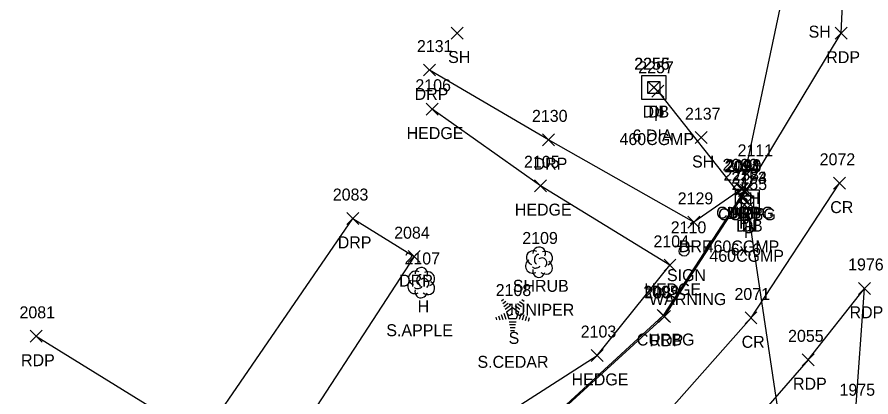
# Model space of a CAD drawing. Extents: x 462930 to 463548, y 29607 to 30453.
# Drawn here: x 463350.88 to 463394.45, y 30226.91 to 30246.27 of the extents above; entities that cross this region are included whole.
import ezdxf

# ---------------------------------------------------------------- set-up
doc = ezdxf.new("R2010")
doc.units = 0
for name, color, linetype in [('D_A', 7, 'Continuous'), ('D_C', 7, 'Continuous'), ('D_I', 7, 'Continuous'), ('D_TIC', 7, 'Continuous'), ('DCP', 7, 'Continuous'), ('DS', 7, 'Continuous'), ('L_A', 7, 'Continuous'), ('L_C', 7, 'Continuous'), ('L_I', 7, 'Continuous'), ('L_TIC', 7, 'Continuous'), ('LAHR', 7, 'Continuous'), ('LSH', 7, 'Continuous'), ('LTC', 7, 'Continuous'), ('LTD', 7, 'Continuous'), ('P_A', 7, 'Continuous'), ('P_I', 7, 'Continuous'), ('P_TIC', 7, 'Continuous'), ('PET', 7, 'Continuous'), ('PRC', 7, 'Continuous'), ('R_A', 7, 'Continuous'), ('R_I', 7, 'Continuous'), ('R_TIC', 7, 'Continuous'), ('RC', 7, 'Continuous'), ('RDP', 7, 'Continuous'), ('S_A', 7, 'Continuous'), ('S_C', 7, 'Continuous'), ('S_I', 7, 'Continuous'), ('SSGN', 7, 'Continuous')]:
    doc.layers.add(name, color=color, linetype=linetype)

msp = doc.modelspace()

# ---------------------------------------------------------------- linework, layer by layer
at = {"layer": 'D_TIC'}
for points in [[(463383.071, 30242.367), (463383.681, 30242.977)], [(463383.681, 30242.367), (463383.071, 30242.977)], [(463383.268, 30242.182), (463383.878, 30242.792)], [(463383.878, 30242.182), (463383.268, 30242.792)], [(463387.614, 30236.711), (463388.224, 30237.321)], [(463388.224, 30236.711), (463387.614, 30237.321)], [(463387.844, 30236.554), (463388.454, 30237.164)], [(463388.454, 30236.554), (463387.844, 30237.164)], [(463387.855, 30236.235), (463388.465, 30236.845)], [(463388.465, 30236.235), (463387.855, 30236.845)]]:
    msp.add_lwpolyline(points, dxfattribs=at)
at = {"layer": 'DCP'}
for points in [[(463383.573, 30242.487), (463387.919, 30237.016)], [(463388.16, 30236.54), (463390.706, 30219.484)]]:
    msp.add_lwpolyline(points, dxfattribs=at)
at = {"layer": 'DS'}
for p, q in [((463382.765, 30243.281), (463383.984, 30243.281)), ((463382.765, 30242.062), (463382.765, 30243.281)), ((463383.984, 30243.281), (463383.984, 30242.062)), ((463383.07, 30242.367), (463383.07, 30242.976)), ((463383.07, 30242.976), (463383.679, 30242.976)), ((463383.376, 30242.672), (463383.376, 30242.672)), ((463383.376, 30242.672), (463383.376, 30242.672)), ((463383.679, 30242.976), (463383.679, 30242.367)), ((463383.679, 30242.367), (463383.07, 30242.367)), ((463383.984, 30242.062), (463382.765, 30242.062)), ((463387.538, 30237.468), (463388.757, 30237.468)), ((463387.538, 30236.249), (463387.538, 30237.468)), ((463388.757, 30237.468), (463388.757, 30236.249)), ((463387.843, 30236.554), (463387.843, 30237.163)), ((463387.843, 30237.163), (463388.452, 30237.163)), ((463388.452, 30237.163), (463388.452, 30236.554)), ((463388.452, 30236.554), (463387.843, 30236.554)), ((463388.149, 30236.859), (463388.149, 30236.859)), ((463388.149, 30236.859), (463388.149, 30236.859)), ((463388.757, 30236.249), (463387.538, 30236.249))]:
    msp.add_line(p, q, dxfattribs=at)
at = {"layer": 'L_TIC'}
for points in [[(463373.034, 30245.145), (463373.644, 30245.755)], [(463373.644, 30245.145), (463373.034, 30245.755)], [(463371.764, 30241.269), (463372.374, 30241.879)], [(463372.374, 30241.269), (463371.764, 30241.879)], [(463385.48, 30239.82), (463386.09, 30240.43)], [(463386.09, 30239.82), (463385.48, 30240.43)], [(463387.819, 30237.952), (463388.429, 30238.562)], [(463388.429, 30237.952), (463387.819, 30238.562)], [(463377.287, 30237.369), (463377.897, 30237.979)], [(463377.897, 30237.369), (463377.287, 30237.979)], [(463383.894, 30233.312), (463384.504, 30233.922)], [(463384.504, 30233.312), (463383.894, 30233.922)], [(463380.183, 30228.717), (463380.793, 30229.327)], [(463380.793, 30228.717), (463380.183, 30229.327)]]:
    msp.add_lwpolyline(points, dxfattribs=at)
at = {"layer": 'LAHR'}
msp.add_lwpolyline([(463364.966, 30224.308), (463371.552, 30223.305), (463380.488, 30229.022), (463384.199, 30233.617), (463377.592, 30237.674), (463372.069, 30241.574)], dxfattribs=at)
at = {"layer": 'LSH'}
msp.add_line((463377.51, 30233.791), (463377.51, 30233.791), dxfattribs=at)
msp.add_line((463377.51, 30233.791), (463377.51, 30233.791), dxfattribs=at)
msp.add_arc((463377.524, 30234.228), 0.319, 335.5272, 180.9563, dxfattribs=at)
for centre, major_axis, ratio, start_param, end_param in [((463377.269, 30233.994), (0.369, -0.156), 0.895232, 1.570796, 4.712389), ((463377.827, 30233.969), (-0.348, -0.147), 0.949671, 1.570796, 4.712389), ((463377.18, 30233.575), (0.178, -0.317), 0.959034, 3.141593, 6.283185), ((463377.446, 30233.931), (-0.063, -0.241), 0.645439, 3.141593, 6.283185), ((463377.662, 30233.74), (-0.152, 0.203), 0.989748, 3.141593, 6.283185), ((463377.51, 30233.334), (0.081, 0.323), 0.942809, 1.570796, 4.712389), ((463377.37, 30233.562), (-0.19, -0.025), 0.423636, 0, 3.141593), ((463377.815, 30233.537), (-0.332, 0.241), 0.841452, 1.570796, 4.712389)]:
    msp.add_ellipse(centre, major_axis=major_axis, ratio=ratio, start_param=start_param, end_param=end_param, dxfattribs=at)
at = {"layer": 'LTC'}
for p, q in [((463375.6, 30231.809), (463375.708, 30231.888)), ((463375.664, 30231.667), (463375.825, 30231.784)), ((463375.728, 30231.525), (463375.942, 30231.681)), ((463376.41, 30231.67), (463376.617, 30231.519)), ((463376.523, 30231.776), (463376.69, 30231.654)), ((463376.636, 30231.882), (463376.763, 30231.789)), ((463375.792, 30231.383), (463376.059, 30231.578)), ((463375.86, 30231.245), (463376.168, 30231.468)), ((463375.86, 30231.245), (463375.978, 30230.881)), ((463376.168, 30231.468), (463376.472, 30231.247)), ((463376.296, 30231.564), (463376.543, 30231.384)), ((463376.472, 30231.247), (463376.353, 30230.881)), ((463375.305, 30230.98), (463375.351, 30230.837)), ((463375.444, 30231.046), (463375.508, 30230.847)), ((463375.583, 30231.112), (463375.665, 30230.857)), ((463375.721, 30231.178), (463375.822, 30230.867)), ((463376.353, 30230.881), (463375.978, 30230.881)), ((463376.606, 30231.165), (463376.503, 30230.848)), ((463376.741, 30231.089), (463376.653, 30230.819)), ((463376.877, 30231.012), (463376.804, 30230.79)), ((463377.012, 30230.936), (463376.955, 30230.761)), ((463376.341, 30230.728), (463375.992, 30230.728)), ((463376.316, 30230.576), (463376.015, 30230.576)), ((463376.29, 30230.424), (463376.037, 30230.424)), ((463376.265, 30230.271), (463376.059, 30230.271))]:
    msp.add_line(p, q, dxfattribs=at)
at = {"layer": 'LTD'}
msp.add_line((463371.495, 30232.748), (463371.495, 30232.748), dxfattribs=at)
msp.add_line((463371.495, 30232.748), (463371.495, 30232.748), dxfattribs=at)
msp.add_arc((463371.509, 30233.185), 0.319, 335.5272, 180.9563, dxfattribs=at)
for centre, major_axis, ratio, start_param, end_param in [((463371.254, 30232.951), (0.369, -0.156), 0.895232, 1.570796, 4.712389), ((463371.431, 30232.888), (-0.063, -0.241), 0.645439, 3.141593, 6.283185), ((463371.647, 30232.697), (-0.152, 0.203), 0.989748, 3.141593, 6.283185), ((463371.812, 30232.926), (-0.348, -0.147), 0.949671, 1.570796, 4.712389), ((463371.165, 30232.532), (0.178, -0.317), 0.959034, 3.141593, 6.283185), ((463371.355, 30232.519), (-0.19, -0.025), 0.423636, 0, 3.141593), ((463371.8, 30232.494), (-0.332, 0.241), 0.841452, 1.570796, 4.712389), ((463371.495, 30232.291), (0.081, 0.323), 0.942809, 1.570796, 4.712389)]:
    msp.add_ellipse(centre, major_axis=major_axis, ratio=ratio, start_param=start_param, end_param=end_param, dxfattribs=at)
at = {"layer": 'P_TIC'}
for points in [[(463392.636, 30245.137), (463393.246, 30245.747)], [(463393.246, 30245.137), (463392.636, 30245.747)], [(463387.794, 30237.145), (463388.404, 30237.755)], [(463388.404, 30237.145), (463387.794, 30237.755)], [(463392.55, 30237.495), (463393.16, 30238.105)], [(463393.16, 30237.495), (463392.55, 30238.105)], [(463393.822, 30232.137), (463394.432, 30232.747)], [(463394.432, 30232.137), (463393.822, 30232.747)], [(463383.613, 30230.708), (463384.223, 30231.318)], [(463384.223, 30230.708), (463383.613, 30231.318)], [(463388.028, 30230.631), (463388.638, 30231.241)], [(463388.638, 30230.631), (463388.028, 30231.241)], [(463351.544, 30229.696), (463352.154, 30230.306)], [(463352.154, 30229.696), (463351.544, 30230.306)], [(463390.938, 30228.498), (463391.548, 30229.108)], [(463391.548, 30228.498), (463390.938, 30229.108)]]:
    msp.add_lwpolyline(points, dxfattribs=at)
at = {"layer": 'PET'}
for points in [[(463351.849, 30230.001), (463360.302, 30224.79), (463363.81, 30222.829), (463366.719, 30221.627), (463371.212, 30221.775), (463377.641, 30225.283), (463383.918, 30231.013), (463388.099, 30237.45), (463392.941, 30245.442), (463393.346, 30254.193)], [(463384.995, 30204.976), (463390.581, 30216.231), (463393.671, 30226.056), (463394.127, 30232.442)], [(463391.243, 30228.803), (463394.127, 30232.442)], [(463391.243, 30228.803), (463383.284, 30219.654), (463378.918, 30214.508), (463373.68, 30208.043), (463363.064, 30214.586), (463356.837, 30205.224), (463346.241, 30211.421)]]:
    msp.add_lwpolyline(points, dxfattribs=at)
at = {"layer": 'PRC'}
msp.add_lwpolyline([(463348.312, 30227.836), (463361.835, 30219.563), (463370.226, 30217.343), (463379.946, 30221.462), (463388.333, 30230.936), (463392.855, 30237.8)], dxfattribs=at)
at = {"layer": 'R_TIC'}
for points in [[(463371.629, 30243.264), (463372.239, 30243.874)], [(463372.239, 30243.264), (463371.629, 30243.874)], [(463377.699, 30239.708), (463378.309, 30240.318)], [(463378.309, 30239.708), (463377.699, 30240.318)], [(463387.548, 30237.193), (463388.158, 30237.803)], [(463388.158, 30237.193), (463387.548, 30237.803)], [(463387.593, 30237.214), (463388.203, 30237.824)], [(463388.203, 30237.214), (463387.593, 30237.824)], [(463387.694, 30237.129), (463388.304, 30237.739)], [(463388.304, 30237.129), (463387.694, 30237.739)], [(463367.705, 30235.699), (463368.315, 30236.309)], [(463368.315, 30235.699), (463367.705, 30236.309)], [(463385.111, 30235.505), (463385.721, 30236.115)], [(463385.721, 30235.505), (463385.111, 30236.115)], [(463370.836, 30233.754), (463371.446, 30234.364)], [(463371.446, 30233.754), (463370.836, 30234.364)], [(463383.547, 30230.749), (463384.157, 30231.359)], [(463384.157, 30230.749), (463383.547, 30231.359)]]:
    msp.add_lwpolyline(points, dxfattribs=at)
at = {"layer": 'RC'}
msp.add_lwpolyline([(463387.898, 30237.519), (463387.999, 30237.434), (463383.852, 30231.054), (463377.627, 30225.328), (463371.191, 30221.845), (463366.777, 30221.714), (463364.009, 30222.795), (463364.076, 30222.945)], dxfattribs=at)
at = {"layer": 'RDP'}
for points in [[(463391.75, 30255.876), (463387.853, 30237.498), (463385.416, 30235.81), (463378.004, 30240.013), (463371.934, 30243.569)], [(463360.302, 30224.79), (463368.01, 30236.004), (463371.141, 30234.059), (463363.81, 30222.829)]]:
    msp.add_lwpolyline(points, dxfattribs=at)
at = {"layer": 'SSGN'}
for p, q in [((463384.415, 30234.594), (463385.431, 30234.594)), ((463384.917, 30234.34), (463384.917, 30234.34))]:
    msp.add_line(p, q, dxfattribs=at)
msp.add_circle((463384.917, 30234.34), 0.254, dxfattribs=at)

# ---------------------------------------------------------------- texts
at = {"layer": 'D_A'}
for s, height, p in [('DIB', 0.6096, (463382.798, 30241.148)), ('DI', 0.6096, (463383.088, 30241.148)), ('P', 0.61, (463383.383, 30240.963)), ('P', 0.61, (463387.729, 30235.492)), ('DIB', 0.6096, (463387.571, 30235.335)), ('DI', 0.6096, (463387.861, 30235.335)), ('P', 0.61, (463387.97, 30235.016))]:
    msp.add_text(s, height=height, dxfattribs=at).set_placement(p)
at = {"layer": 'D_C'}
for s, p in [('460CGMP', (463381.622, 30239.744)), ('.6 DIA', (463382.063, 30239.929)), ('460CGMP', (463385.968, 30234.273)), ('.6x.6', (463387.071, 30234.116)), ('460CGMP', (463386.209, 30233.797))]:
    msp.add_text(s, height=0.6096, dxfattribs=at).set_placement(p)
at = {"layer": 'D_I'}
for s, p in [('2256', (463382.366, 30243.586)), ('2255', (463382.382, 30243.586)), ('2257', (463382.579, 30243.401)), ('2258', (463386.925, 30237.93)), ('2153', (463387.328, 30237.773)), ('2154', (463387.328, 30237.773)), ('2155', (463387.339, 30237.454))]:
    msp.add_text(s, height=0.6096, dxfattribs=at).set_placement(p)
at = {"layer": 'L_A'}
for s, height, p in [('SH', 0.6096, (463391.272, 30245.219)), ('SH', 0.6096, (463372.878, 30243.926)), ('HEDGE', 0.6096, (463370.759, 30240.05)), ('SH', 0.6096, (463385.324, 30238.601)), ('SH', 0.6096, (463387.663, 30236.733)), ('HEDGE', 0.6096, (463376.282, 30236.15)), ('SHRUB', 0.6096, (463376.178, 30232.267)), ('HEDGE', 0.6096, (463382.889, 30232.093)), ('H', 0.61, (463371.322, 30231.224)), ('S', 0.61, (463375.963, 30229.612)), ('HEDGE', 0.6096, (463379.178, 30227.498))]:
    msp.add_text(s, height=height, dxfattribs=at).set_placement(p)
at = {"layer": 'L_C'}
for s, p in [('JUNIPER', (463375.828, 30231.048)), ('S.APPLE', (463369.724, 30230.005)), ('S.CEDAR', (463374.376, 30228.393))]:
    msp.add_text(s, height=0.6096, dxfattribs=at).set_placement(p)
at = {"layer": 'L_I'}
for s, p in [('2106', (463371.207, 30242.488)), ('2137', (463384.964, 30241.039)), ('2111', (463387.649, 30239.171)), ('2105', (463376.747, 30238.588)), ('2109', (463376.663, 30234.705)), ('2104', (463383.354, 30234.531)), ('2107', (463370.65, 30233.662)), ('2108', (463375.305, 30232.05)), ('2103', (463379.643, 30229.936))]:
    msp.add_text(s, height=0.6096, dxfattribs=at).set_placement(p)
at = {"layer": 'LTC'}
msp.add_text('.', height=0.316, rotation=270, dxfattribs=at).set_placement((463376.133, 30231.168))
at = {"layer": 'P_A'}
for s, p in [('RDP', (463392.175, 30243.918)), ('CR', (463392.377, 30236.276)), ('RDP', (463387.333, 30235.926)), ('RDP', (463393.361, 30230.918)), ('RDP', (463383.152, 30229.489)), ('CR', (463387.855, 30229.412)), ('RDP', (463351.083, 30228.477)), ('RDP', (463390.477, 30227.279))]:
    msp.add_text(s, height=0.6096, dxfattribs=at).set_placement(p)
at = {"layer": 'P_I'}
for s, p in [('2072', (463391.837, 30238.714)), ('2090', (463387.055, 30238.364)), ('1976', (463393.289, 30233.356)), ('2089', (463382.898, 30231.927)), ('2071', (463387.488, 30231.85)), ('2081', (463351.004, 30230.915)), ('2055', (463390.225, 30229.717)), ('1975', (463392.85, 30226.97))]:
    msp.add_text(s, height=0.6096, dxfattribs=at).set_placement(p)
at = {"layer": 'R_A'}
for s, p in [('DRP', (463371.168, 30242.045)), ('DRP', (463377.238, 30238.489)), ('CURBG', (463386.552, 30235.995)), ('CURBG', (463386.653, 30235.91)), ('DRP', (463387.087, 30235.974)), ('DRP', (463367.244, 30234.48)), ('DRP', (463384.65, 30234.286)), ('DRP', (463370.375, 30232.535)), ('CURBG', (463382.506, 30229.53))]:
    msp.add_text(s, height=0.6096, dxfattribs=at).set_placement(p)
at = {"layer": 'R_I'}
for s, p in [('2131', (463371.286, 30244.483)), ('2130', (463377.157, 30240.927)), ('2093', (463386.88, 30238.433)), ('2094', (463386.981, 30238.348)), ('2128', (463387.032, 30238.412)), ('2083', (463366.992, 30236.918)), ('2129', (463384.593, 30236.724)), ('2084', (463370.123, 30234.973)), ('2095', (463382.834, 30231.968))]:
    msp.add_text(s, height=0.6096, dxfattribs=at).set_placement(p)
at = {"layer": 'S_A'}
msp.add_text('SIGN', height=0.6096, dxfattribs=at).set_placement((463384.045, 30232.81))
at = {"layer": 'S_C'}
msp.add_text('WARNING', height=0.6096, dxfattribs=at).set_placement((463383.133, 30231.591))
at = {"layer": 'S_I'}
msp.add_text('2110', height=0.6096, dxfattribs=at).set_placement((463384.237, 30235.248))

doc.saveas('drawing.dxf')
